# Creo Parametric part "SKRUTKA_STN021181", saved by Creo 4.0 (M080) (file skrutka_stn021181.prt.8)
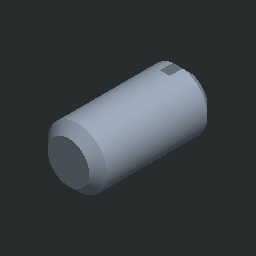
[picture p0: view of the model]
Units: Custom; MM, KILOGRAM, SECS
Materials in the file: OCEL, OCEL_N

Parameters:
  PTC_MATERIAL_NAME = "OCEL"
  NAZOV = "SKRUTKA_STN021181"
  NORMA = "STN 02 1181"

Other parameters: HMOTNOST, HUSTOTA, D11

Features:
  1. chamfer
  2. chamfer
  3. datum plane "DTM3"
  4. datum plane "DTM5"
  5. datum plane "DTM6"

Other named items: THRU

Layers: 1, 2, 3, 4, 5, 6, 7, 8, 9, 10, 11, 12, 13, 14, 15, 16, 17, 18, 19, 20, 21, 22, 23, 24, 25, 26, 27, 28, 29, 30, 31, 32

Family table entries: GENERIC, SKRUTKA_M1_6, SKRUTKA_STN021181, value(d_val), value(i_val), SKRUTKA_M2, SKRUTKA_STN021181, SKRUTKA_M2_5, SKRUTKA_STN021181, SKRUTKA_M3, SKRUTKA_STN021181, SKRUTKA_M3_5, SKRUTKA_STN021181, SKRUTKA_M4, SKRUTKA_STN021181, SKRUTKA_M5, SKRUTKA_STN021181, SKRUTKA_M6, SKRUTKA_STN021181, SKRUTKA_M8, SKRUTKA_STN021181, !/ , SKRUTKA_M10, SKRUTKA_STN021181, !/$, SKRUTKA_M12, SKRUTKA_STN021181, !/(, # Pro/TABLE, [] S 92;, [] W 10;, [A] W  3;, [B] W 13;, [C] W 10;, [D] W 10;, [E] W 10;, [F] W 10;, [G] W 10;

Surfaces: 7 plane, 3 cylinder, 3 cone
